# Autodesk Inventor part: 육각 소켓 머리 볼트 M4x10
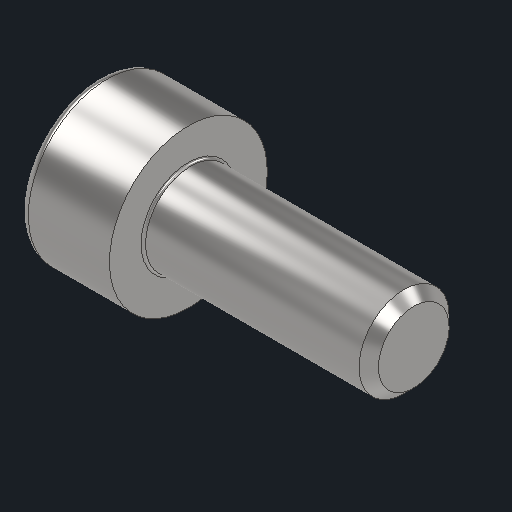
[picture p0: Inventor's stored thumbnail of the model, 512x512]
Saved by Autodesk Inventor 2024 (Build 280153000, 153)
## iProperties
Created: 2024-05
Part Number: 육각 소켓 머리 볼트 M4x10
Material: 강철, 연강
Description: 6각머리 태핑 나사
Document SubType Name: Modeling
Designer: kh_501
Mass: 2.03451 g
Surface Area: 3.0572 cm^2
Volume: 0.259174 cm^3
Density: 7.85 g/cm^3
Appearance: 기본값
Author: jhkim
Sending System: Autodesk Inventor 2025
Preprocessor: ST-DEVELOPER v20
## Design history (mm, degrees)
node "육각 소켓 머리 볼트 M4x101"
node "솔리드1"
body "Solid1"
